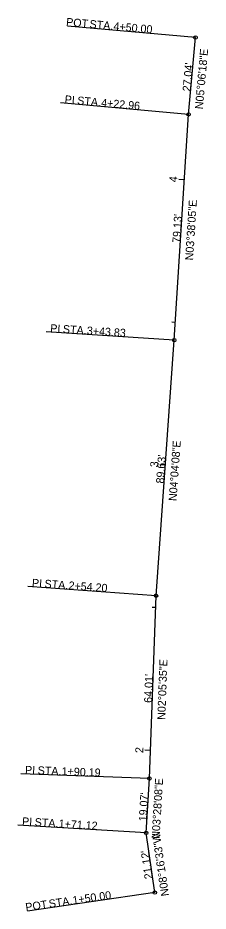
# Model space of a CAD drawing. Extents: x 2382161 to 2382228, y 257738 to 258051.
import ezdxf

# ---------------------------------------------------------------- set-up
doc = ezdxf.new("R2010")
doc.units = 0
for name, color, linetype in [('RW_X_CL_100_Bearings', 7, 'Continuous'), ('RW_X_CL_100_Cardinal_Points', 7, 'Continuous'), ('RW_X_CL_100_Curve_Data', 7, 'Continuous'), ('RW_X_CL_100_Stations', 7, 'Continuous'), ('RW_X_Esmt_SH', 7, 'Continuous')]:
    doc.layers.add(name, color=color, linetype=linetype)

msp = doc.modelspace()

# ---------------------------------------------------------------- linework, layer by layer
at = {"layer": 'RW_X_CL_100_Cardinal_Points'}
for p, q in [((2382223.1, 258043.95), (2382178.28, 258047.95)), ((2382220.69, 258017.01), (2382175.87, 258021.02)), ((2382215.68, 257938.04), (2382170.77, 257940.9)), ((2382209.32, 257848.63), (2382164.43, 257851.83)), ((2382206.98, 257784.67), (2382162.01, 257786.31)), ((2382205.83, 257765.63), (2382160.91, 257768.36)), ((2382208.87, 257744.74), (2382164.33, 257738.26))]:
    msp.add_line(p, q, dxfattribs=at)
for centre in [(2382223.1, 258043.95), (2382220.69, 258017.01), (2382215.68, 257938.04), (2382209.32, 257848.63), (2382206.98, 257784.67), (2382205.83, 257765.63), (2382208.87, 257744.74)]:
    msp.add_circle(centre, 0.6, dxfattribs=at)
at = {"layer": 'RW_X_CL_100_Stations'}
for p, q in [((2382223.1, 258043.95), (2382221.91, 258044.05)), ((2382219.24, 257994.1), (2382217.24, 257994.23)), ((2382216.07, 257944.2), (2382214.87, 257944.28)), ((2382212.57, 257894.32), (2382210.57, 257894.47)), ((2382209.16, 257844.44), (2382207.96, 257844.49)), ((2382207.34, 257794.48), (2382205.34, 257794.55)), ((2382208.87, 257744.74), (2382207.68, 257744.56))]:
    msp.add_line(p, q, dxfattribs=at)
at = {"layer": 'RW_X_Esmt_SH'}
for p, q in [((2382220.69, 258017.01), (2382223.1, 258043.95)), ((2382215.68, 257938.04), (2382220.69, 258017.01)), ((2382209.32, 257848.63), (2382215.68, 257938.04)), ((2382206.98, 257784.67), (2382209.32, 257848.63)), ((2382205.83, 257765.63), (2382206.98, 257784.67)), ((2382208.87, 257744.74), (2382205.83, 257765.63))]:
    msp.add_line(p, q, dxfattribs=at)

# ---------------------------------------------------------------- texts
at = {"layer": 'RW_X_CL_100_Bearings'}
for s, rotation, p in [('N05°06\'18"E', 84.8949, (2382225.67, 258018.74)), ('N03°38\'05"E', 86.3652, (2382222.26, 257965.88)), ('N04°04\'08"E', 85.931, (2382216.48, 257881.66)), ('N02°05\'35"E', 87.9069, (2382212.53, 257805.12)), ('N03°28\'08"E', 86.5312, (2382210.51, 257763.52)), ('N08°16\'33"W', 98.276, (2382213.87, 257743.69))]:
    msp.add_text(s, height=2.8, rotation=rotation, dxfattribs=at).set_placement(p)
at = {"layer": 'RW_X_CL_100_Cardinal_Points'}
for s, rotation, p in [('POT', 354.8949, (2382177.72, 258048.04)), (' STA. ', 354.8949, (2382184.89, 258047.4)), ('4+50.00', 354.8949, (2382194.31, 258046.56)), ('PI', 354.8949, (2382177.2, 258020.94)), (' STA. ', 354.8949, (2382180.58, 258020.64)), ('4+22.96', 354.8949, (2382189.99, 258019.8)), ('PI', 356.3652, (2382172.18, 257940.85)), (' STA. ', 356.3652, (2382175.57, 257940.63)), ('3+43.83', 356.3652, (2382185, 257940.03)), ('PI', 355.931, (2382165.77, 257851.77)), (' STA. ', 355.931, (2382169.15, 257851.53)), ('2+54.20', 355.931, (2382178.58, 257850.86)), ('PI', 357.9069, (2382163.38, 257786.3)), (' STA. ', 357.9069, (2382166.77, 257786.18)), ('1+90.19', 357.9069, (2382176.21, 257785.83)), ('PI', 356.5312, (2382162.32, 257768.31)), (' STA. ', 356.5312, (2382165.7, 257768.11)), ('1+71.12', 356.5312, (2382175.14, 257767.53)), ('1+50.00', 8.276, (2382180.25, 257740.62)), ('POT', 8.276, (2382163.77, 257738.22)), (' STA. ', 8.276, (2382170.9, 257739.26))]:
    msp.add_text(s, height=2.8, rotation=rotation, dxfattribs=at).set_placement(p)
at = {"layer": 'RW_X_CL_100_Curve_Data'}
for s, rotation, p in [("27.04'", 84.8949, (2382221.36, 258024.94)), ("79.13'", 86.3652, (2382217.79, 257971.98)), ("89.63'", 85.931, (2382212.06, 257887.79)), ("64.01'", 87.9069, (2382207.9, 257811.09)), ("19.07'", 86.5312, (2382206.02, 257769.6)), ("21.12'", 98.276, (2382208.13, 257749.68))]:
    msp.add_text(s, height=2.8, rotation=rotation, dxfattribs=at).set_placement(p)
at = {"layer": 'RW_X_CL_100_Stations'}
for s, rotation, p in [('4', 86.3652, (2382216.68, 257993.22)), ('3', 85.931, (2382210, 257893.47)), ('2', 87.9069, (2382204.8, 257793.52))]:
    msp.add_text(s, height=2.8, rotation=rotation, dxfattribs=at).set_placement(p)

doc.saveas('drawing.dxf')
